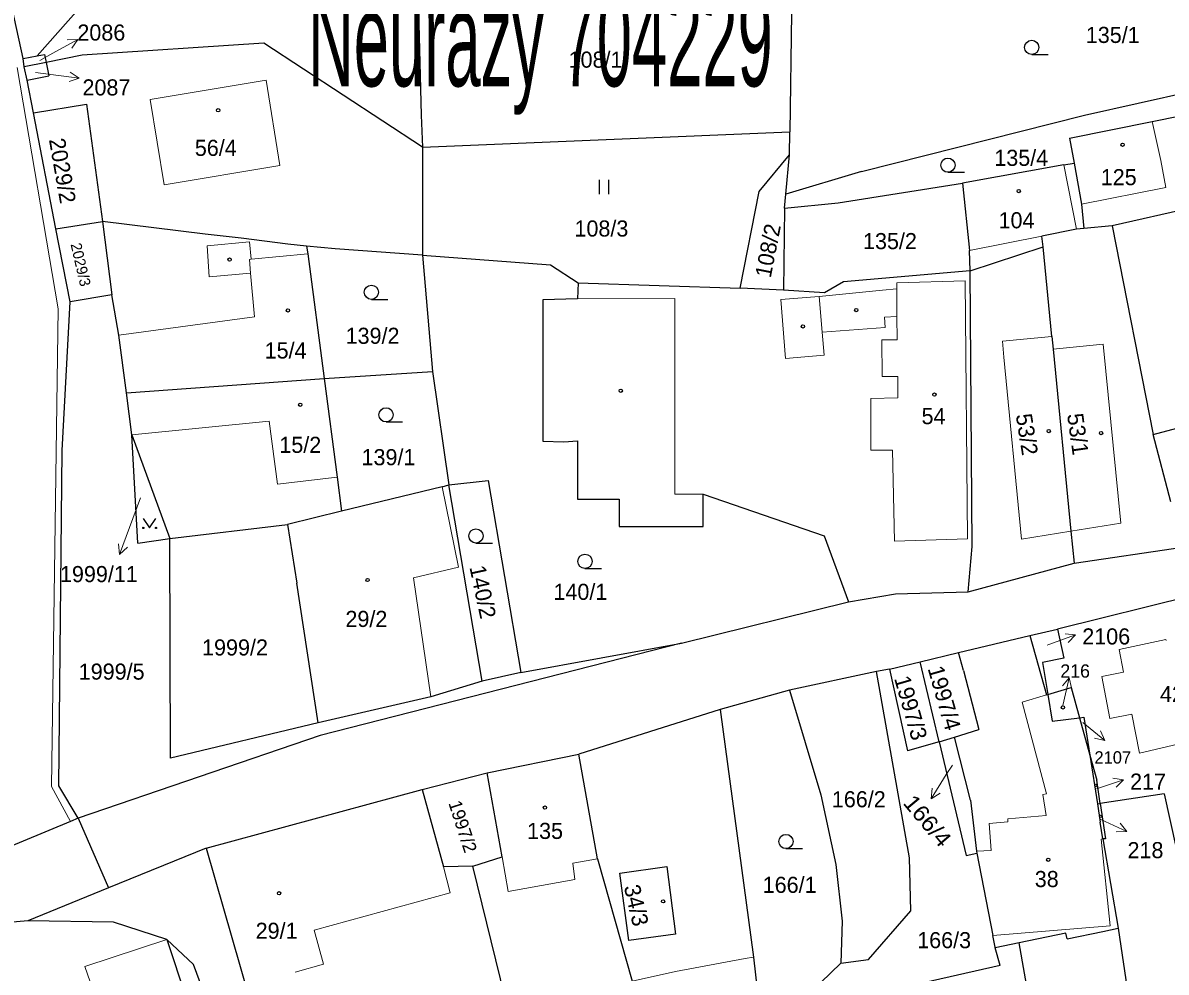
# Model space of a CAD drawing. Extents: x -820420 to -815896, y -1105820 to -1103643.
# Drawn here: x -817654.9 to -817534.2, y -1104919.6 to -1104819.4 of the extents above; entities that cross this region are included whole.
import ezdxf
from ezdxf.enums import TextEntityAlignment as Align

# ---------------------------------------------------------------- set-up
doc = ezdxf.new("R2010")
doc.units = 0
doc.header["$LTSCALE"] = 0.68
for name, color, linetype, lineweight in [('1', 7, 'Continuous', 25), ('3', 7, 'Continuous', 25), ('4', 7, 'Continuous', 13), ('5', 7, 'Continuous', 25), ('7', 7, 'Continuous', 13)]:
    doc.layers.add(name, color=color, linetype=linetype, lineweight=lineweight)
doc.layers.add('2', color=7, linetype='Continuous')

msp = doc.modelspace()

# ---------------------------------------------------------------- linework, layer by layer
at = {"layer": '1'}
for p, q in [((-817654.9, -1104823.17), (-817658.74, -1104805.43)), ((-817653.43, -1104822.89), (-817640.64, -1104808.45)), ((-817613.34, -1104810.6), (-817612.89, -1104829.14)), ((-817573.78, -1104818.38), (-817573.97, -1104830.9)), ((-817629.5, -1104821.54), (-817648.67, -1104822.8)), ((-817612.76, -1104832.53), (-817629.5, -1104821.54)), ((-817654.9, -1104823.17), (-817653.43, -1104822.89)), ((-817654.78, -1104824.05), (-817654.9, -1104823.17)), ((-817653.43, -1104822.89), (-817652.64, -1104822.74)), ((-817652.64, -1104822.74), (-817652.48, -1104823.58)), ((-817648.67, -1104822.8), (-817652.48, -1104823.58)), ((-817542.88, -1104829.13), (-817516.28, -1104823.19)), ((-817652.48, -1104823.58), (-817654.78, -1104824.05)), ((-817654.47, -1104825.45), (-817654.78, -1104824.05)), ((-817652.48, -1104823.58), (-817652.19, -1104824.98)), ((-817654.47, -1104825.45), (-817652.19, -1104824.98)), ((-817653.82, -1104828.9), (-817654.47, -1104825.45)), ((-817653.82, -1104828.9), (-817648.21, -1104827.97)), ((-817648.21, -1104827.97), (-817646.54, -1104840.38)), ((-817651.45, -1104841.15), (-817653.82, -1104828.9)), ((-817612.89, -1104829.14), (-817612.76, -1104832.53)), ((-817566.42, -1104835.1), (-817542.88, -1104829.13)), ((-817535.71, -1104829.81), (-817532.77, -1104829.22)), ((-817544.44, -1104831.56), (-817535.71, -1104829.81)), ((-817612.76, -1104832.53), (-817573.97, -1104830.9)), ((-817574.01, -1104833.33), (-817573.97, -1104830.9)), ((-817544.44, -1104831.56), (-817543.97, -1104834.2)), ((-817612.76, -1104832.53), (-817612.75, -1104843.92)), ((-817577.19, -1104837.21), (-817574.01, -1104833.33)), ((-817574.4, -1104837.48), (-817574.01, -1104833.33)), ((-817566.42, -1104835.1), (-817574.4, -1104837.48)), ((-817545.03, -1104834.37), (-817555.75, -1104836.32)), ((-817545.03, -1104834.37), (-817543.97, -1104834.2)), ((-817543.97, -1104834.2), (-817543.19, -1104838.54)), ((-817568.85, -1104838.39), (-817555.75, -1104836.32)), ((-817555.75, -1104836.32), (-817555.02, -1104843.43)), ((-817574.54, -1104838.95), (-817574.4, -1104837.48)), ((-817574.54, -1104838.95), (-817574.65, -1104847.61)), ((-817574.54, -1104838.95), (-817568.85, -1104838.39)), ((-817543.19, -1104838.54), (-817542.92, -1104841.11)), ((-817530.88, -1104838.78), (-817539.93, -1104840.84)), ((-817651.45, -1104841.15), (-817646.54, -1104840.38)), ((-817649.93, -1104848.83), (-817651.45, -1104841.15)), ((-817646.54, -1104840.38), (-817645.55, -1104848.1)), ((-817635.7, -1104841.71), (-817646.54, -1104840.38)), ((-817543.7, -1104841.18), (-817547.36, -1104841.9)), ((-817542.92, -1104841.11), (-817543.7, -1104841.18)), ((-817539.93, -1104840.84), (-817542.92, -1104841.11)), ((-817539.93, -1104840.84), (-817535.62, -1104862.85)), ((-817631.9, -1104842.12), (-817635.7, -1104841.71)), ((-817626.97, -1104842.77), (-817631.9, -1104842.12)), ((-817547.21, -1104843.03), (-817547.36, -1104841.9)), ((-817624.99, -1104842.97), (-817626.97, -1104842.77)), ((-817624.99, -1104842.97), (-817624.86, -1104843.79)), ((-817621.97, -1104843.25), (-817624.99, -1104842.97)), ((-817624.86, -1104843.79), (-817623.13, -1104856.95)), ((-817612.75, -1104843.92), (-817621.97, -1104843.25)), ((-817554.94, -1104845.57), (-817555.02, -1104843.43)), ((-817554.94, -1104845.57), (-817547.21, -1104843.03)), ((-817546.3, -1104852.5), (-817547.21, -1104843.03)), ((-817612.75, -1104843.92), (-817599.23, -1104844.93)), ((-817612.75, -1104843.92), (-817611.69, -1104856.18)), ((-817599.23, -1104844.93), (-817596.33, -1104846.83)), ((-817554.94, -1104845.57), (-817568.31, -1104846.74)), ((-817554.73, -1104874.66), (-817554.94, -1104845.57)), ((-817596.33, -1104846.83), (-817596.38, -1104848.54)), ((-817596.33, -1104846.83), (-817579.2, -1104847.41)), ((-817568.31, -1104846.74), (-817570.32, -1104847.88)), ((-817645.55, -1104848.1), (-817649.93, -1104848.83)), ((-817644.79, -1104852.37), (-817645.55, -1104848.1)), ((-817596.38, -1104848.54), (-817600.05, -1104848.64)), ((-817600.05, -1104848.64), (-817600.03, -1104863.53)), ((-817570.32, -1104847.88), (-817574.65, -1104847.61)), ((-817650.79, -1104864.54), (-817649.93, -1104848.83)), ((-817643.99, -1104858.45), (-817644.79, -1104852.37)), ((-817546.3, -1104852.5), (-817546.17, -1104853.85)), ((-817546.17, -1104853.85), (-817544.31, -1104873.05)), ((-817535.62, -1104862.85), (-817509.39, -1104855.82)), ((-817643.99, -1104858.45), (-817623.13, -1104856.95)), ((-817623.13, -1104856.95), (-817611.69, -1104856.18)), ((-817623.13, -1104856.95), (-817621.77, -1104867.34)), ((-817611.69, -1104856.18), (-817609.98, -1104868.15)), ((-817643.43, -1104862.87), (-817643.99, -1104858.45)), ((-817642.8, -1104874.31), (-817643.43, -1104862.87)), ((-817643.43, -1104862.87), (-817639.42, -1104873.82)), ((-817533.76, -1104869.95), (-817535.62, -1104862.85)), ((-817600.03, -1104863.53), (-817597.84, -1104863.63)), ((-817597.84, -1104863.63), (-817596.37, -1104863.51)), ((-817596.37, -1104863.51), (-817596.37, -1104869.66)), ((-817651.15, -1104899.91), (-817650.79, -1104864.54)), ((-817621.77, -1104867.34), (-817621.3, -1104870.93)), ((-817609.98, -1104868.15), (-817605.81, -1104867.7)), ((-817605.81, -1104867.7), (-817602.36, -1104887.97)), ((-817610.68, -1104868.37), (-817621.3, -1104870.93)), ((-817610.68, -1104868.37), (-817609.98, -1104868.15)), ((-817606.45, -1104888.88), (-817609.98, -1104868.15)), ((-817583.12, -1104869.15), (-817570.34, -1104873.54)), ((-817583.12, -1104872.54), (-817583.12, -1104869.15)), ((-817596.37, -1104869.66), (-817591.99, -1104869.66)), ((-817591.99, -1104869.66), (-817591.99, -1104872.55)), ((-817621.3, -1104870.93), (-817627, -1104872.33)), ((-817591.99, -1104872.55), (-817583.12, -1104872.54)), ((-817642.8, -1104874.31), (-817639.42, -1104873.82)), ((-817639.36, -1104897), (-817639.42, -1104873.82)), ((-817570.34, -1104873.54), (-817567.78, -1104880.49)), ((-817544.31, -1104873.05), (-817543.97, -1104876.41)), ((-817555.13, -1104879.43), (-817554.73, -1104874.66)), ((-817543.97, -1104876.41), (-817532.5, -1104874.73)), ((-817555.13, -1104879.43), (-817543.97, -1104876.41)), ((-817623.76, -1104893.26), (-817626.03, -1104878.52)), ((-817530.11, -1104879.52), (-817545.73, -1104883.38)), ((-817585.42, -1104884.86), (-817567.78, -1104880.49)), ((-817585.42, -1104884.86), (-817623.55, -1104894.62)), ((-817602.36, -1104887.97), (-817585.42, -1104884.86)), ((-817556.17, -1104885.85), (-817548.63, -1104884.07)), ((-817548.63, -1104884.07), (-817546.87, -1104890.32)), ((-817560.22, -1104886.83), (-817556.17, -1104885.85)), ((-817555.65, -1104887.76), (-817556.17, -1104885.85)), ((-817563.45, -1104887.61), (-817560.22, -1104886.83)), ((-817558.21, -1104895.27), (-817560.22, -1104886.83)), ((-817545.05, -1104886.46), (-817547.28, -1104886.9)), ((-817547.28, -1104886.9), (-817546.74, -1104890.28)), ((-817602.36, -1104887.97), (-817606.45, -1104888.88)), ((-817564.82, -1104887.87), (-817574.01, -1104889.84)), ((-817563.45, -1104887.61), (-817564.82, -1104887.87)), ((-817561.35, -1104907.52), (-817564.82, -1104887.87)), ((-817563.45, -1104887.61), (-817561.56, -1104896.24)), ((-817555.65, -1104887.76), (-817554.01, -1104893.97)), ((-817606.45, -1104888.88), (-817611.88, -1104890.54)), ((-817546.74, -1104890.28), (-817544.28, -1104889.56)), ((-817544.28, -1104889.56), (-817543.4, -1104892.74)), ((-817611.88, -1104890.54), (-817623.76, -1104893.26)), ((-817574.01, -1104889.84), (-817581.32, -1104891.87)), ((-817574.01, -1104889.84), (-817570.68, -1104900.87)), ((-817546.87, -1104890.32), (-817546.74, -1104890.28)), ((-817546.74, -1104890.28), (-817546.29, -1104893.08)), ((-817581.32, -1104891.87), (-817596.25, -1104896.58)), ((-817581.32, -1104891.87), (-817577.81, -1104917.99)), ((-817623.76, -1104893.26), (-817639.36, -1104897)), ((-817546.29, -1104893.08), (-817543.4, -1104892.74)), ((-817543.4, -1104892.74), (-817542.93, -1104892.68)), ((-817543.4, -1104892.74), (-817542.3, -1104896.68)), ((-817623.55, -1104894.62), (-817649.09, -1104903.33)), ((-817558.21, -1104895.27), (-817561.56, -1104896.24)), ((-817554.9, -1104901.44), (-817556.58, -1104894.8)), ((-817605.93, -1104898.54), (-817596.25, -1104896.58)), ((-817594.26, -1104907.62), (-817596.25, -1104896.58)), ((-817542.3, -1104896.68), (-817541.57, -1104899.32)), ((-817612.79, -1104900.31), (-817605.93, -1104898.54)), ((-817604.35, -1104907.42), (-817605.93, -1104898.54)), ((-817541.21, -1104901.78), (-817541.57, -1104899.32)), ((-817649.09, -1104903.33), (-817651.15, -1104899.91)), ((-817635.6, -1104906.5), (-817612.79, -1104900.31)), ((-817612.79, -1104900.31), (-817610.54, -1104908.46)), ((-817570.68, -1104900.87), (-817569.12, -1104908.21)), ((-817554.9, -1104901.44), (-817554.26, -1104906.82)), ((-817541.5, -1104901.82), (-817541.21, -1104901.78)), ((-817534.44, -1104900.75), (-817541.21, -1104901.78)), ((-817541.21, -1104901.78), (-817540.66, -1104905.51)), ((-817534.44, -1104900.75), (-817531.92, -1104912.23)), ((-817541.5, -1104901.82), (-817541.22, -1104903.77)), ((-817649.91, -1104903.67), (-817659.5, -1104907.65)), ((-817649.09, -1104903.33), (-817649.91, -1104903.67)), ((-817649.09, -1104903.33), (-817645.91, -1104910.68)), ((-817540.92, -1104905.53), (-817541.22, -1104903.77)), ((-817635.6, -1104906.5), (-817645.91, -1104910.68)), ((-817635.6, -1104906.5), (-817628.62, -1104930.65)), ((-817540.66, -1104905.51), (-817540.92, -1104905.53)), ((-817540.92, -1104905.53), (-817539.31, -1104914.95)), ((-817607.42, -1104908.4), (-817604.35, -1104907.42)), ((-817594.26, -1104907.62), (-817590.63, -1104920.54)), ((-817561.19, -1104913.11), (-817561.35, -1104907.52)), ((-817554.26, -1104906.82), (-817554.22, -1104907.03)), ((-817554.22, -1104907.03), (-817552.54, -1104915.72)), ((-817607.42, -1104908.4), (-817610.54, -1104908.46)), ((-817603.85, -1104922.94), (-817607.42, -1104908.4)), ((-817591.93, -1104909.12), (-817586.97, -1104908.43)), ((-817586.97, -1104908.43), (-817586.03, -1104915.58)), ((-817569.12, -1104908.21), (-817568.43, -1104914.19)), ((-817590.97, -1104916.25), (-817591.93, -1104909.12)), ((-817645.91, -1104910.68), (-817654.42, -1104914.15)), ((-817565.67, -1104918.24), (-817561.19, -1104913.11)), ((-817654.42, -1104914.15), (-817660, -1104914.69)), ((-817645.35, -1104914.31), (-817654.42, -1104914.15)), ((-817639.74, -1104916.15), (-817645.35, -1104914.31)), ((-817568.43, -1104914.19), (-817568.58, -1104918.64)), ((-817540.92, -1104915.28), (-817539.31, -1104914.95)), ((-817539.31, -1104914.95), (-817536.86, -1104931.17)), ((-817639.74, -1104916.15), (-817636.91, -1104918.76)), ((-817639.74, -1104916.15), (-817636.38, -1104926.16)), ((-817586.03, -1104915.58), (-817590.97, -1104916.25)), ((-817552.3, -1104916.96), (-817552.54, -1104915.72)), ((-817544.82, -1104915.48), (-817549.77, -1104916.5)), ((-817544.7, -1104916.06), (-817544.82, -1104915.48)), ((-817544.7, -1104916.06), (-817540.92, -1104915.28)), ((-817552.28, -1104917.02), (-817552.3, -1104916.96)), ((-817549.77, -1104916.5), (-817552.28, -1104917.02)), ((-817551.75, -1104918.88), (-817552.28, -1104917.02)), ((-817548.33, -1104924.49), (-817549.77, -1104916.5)), ((-817577.81, -1104917.99), (-817577.4, -1104921.73)), ((-817568.58, -1104918.64), (-817570.71, -1104920.67)), ((-817568.58, -1104918.64), (-817565.67, -1104918.24)), ((-817633.72, -1104927.48), (-817636.91, -1104918.76)), ((-817551.75, -1104918.88), (-817563.41, -1104921.51))]:
    msp.add_line(p, q, dxfattribs=at)
for points in [[(-817574.65, -1104847.61), (-817579.2, -1104847.41), (-817577.19, -1104837.21)], [(-817639.42, -1104873.82), (-817627, -1104872.33), (-817626.03, -1104878.52)], [(-817567.78, -1104880.49), (-817562.83, -1104879.65), (-817555.13, -1104879.43)], [(-817548.63, -1104884.07), (-817545.73, -1104883.38), (-817545.05, -1104886.46)], [(-817542.93, -1104892.68), (-817542.3, -1104896.68), (-817541.5, -1104901.82)], [(-817558.21, -1104895.27), (-817556.58, -1104894.8), (-817554.01, -1104893.97)], [(-817558.21, -1104895.27), (-817555.36, -1104907.28), (-817554.22, -1104907.03)]]:
    msp.add_lwpolyline(points, dxfattribs=at)
at = {"layer": '3'}
for p, q in [((-817548.433, -1104822.74), (-817546.683, -1104822.74)), ((-817557.283, -1104835.17), (-817555.533, -1104835.17)), ((-817594.061, -1104837.47), (-817594.061, -1104835.97)), ((-817593.06, -1104837.47), (-817593.06, -1104835.97)), ((-817618.143, -1104848.58), (-817616.393, -1104848.58)), ((-817616.593, -1104861.52), (-817614.843, -1104861.52)), ((-817607.103, -1104874.3), (-817605.353, -1104874.3)), ((-817595.593, -1104876.98), (-817593.843, -1104876.98)), ((-817574.383, -1104906.54), (-817572.633, -1104906.54))]:
    msp.add_line(p, q, dxfattribs=at)
msp.add_lwpolyline([(-817642.22, -1104871.694), (-817641.55, -1104872.7), (-817640.88, -1104871.694)], dxfattribs=at)
for centre, radius in [((-817548.4329, -1104821.9898), 0.75), ((-817557.2829, -1104834.4198), 0.75), ((-817618.1429, -1104847.8298), 0.75), ((-817616.5929, -1104860.7698), 0.75), ((-817642.22, -1104872.6996), 0.067), ((-817640.88, -1104872.6996), 0.067), ((-817607.1029, -1104873.5498), 0.75), ((-817595.5929, -1104876.2298), 0.75), ((-817574.3829, -1104905.7898), 0.75)]:
    msp.add_circle(centre, radius, dxfattribs=at)
at = {"layer": '4'}
for p, q in [((-817651.2, -1104849.57), (-817655.55, -1104824.12)), ((-817641.49, -1104827.48), (-817629.24, -1104825.44)), ((-817629.24, -1104825.44), (-817627.8, -1104834.47)), ((-817640.03, -1104836.5), (-817641.49, -1104827.48)), ((-817640.03, -1104836.5), (-817627.8, -1104834.47)), ((-817543.7, -1104841.18), (-817545.03, -1104834.37)), ((-817543.19, -1104838.54), (-817534.26, -1104836.77)), ((-817631.02, -1104842.52), (-817635.47, -1104842.93)), ((-817631.02, -1104842.52), (-817630.85, -1104844.35)), ((-817555.02, -1104843.43), (-817547.36, -1104841.9)), ((-817635.47, -1104842.93), (-817635.26, -1104846.22)), ((-817630.85, -1104844.35), (-817624.86, -1104843.79)), ((-817631.02, -1104844.37), (-817630.85, -1104844.35)), ((-817631.02, -1104844.37), (-817630.89, -1104845.83)), ((-817635.26, -1104846.22), (-817630.89, -1104845.83)), ((-817630.89, -1104845.83), (-817630.48, -1104850.44)), ((-817562.69, -1104847.48), (-817562.68, -1104846.83)), ((-817562.68, -1104846.83), (-817555.46, -1104846.61)), ((-817555.46, -1104846.61), (-817555.2, -1104873.87)), ((-817596.38, -1104848.54), (-817586.11, -1104848.5)), ((-817586.11, -1104848.5), (-817586.11, -1104869.15)), ((-817574.91, -1104848.61), (-817570.88, -1104848.29)), ((-817574.42, -1104854.83), (-817574.91, -1104848.61)), ((-817570.88, -1104848.29), (-817564.17, -1104847.62)), ((-817570.88, -1104848.29), (-817570.56, -1104852.04)), ((-817564.17, -1104847.62), (-817562.69, -1104847.48)), ((-817651.92, -1104900), (-817651.2, -1104849.57)), ((-817644.79, -1104852.37), (-817630.48, -1104850.44)), ((-817563.96, -1104850.45), (-817563.9, -1104851.55)), ((-817562.65, -1104852.84), (-817562.67, -1104850.38)), ((-817563.9, -1104851.55), (-817570.56, -1104852.04)), ((-817570.56, -1104852.04), (-817570.35, -1104854.48)), ((-817564.24, -1104852.85), (-817562.65, -1104852.84)), ((-817564.22, -1104856.73), (-817564.24, -1104852.85)), ((-817546.3, -1104852.5), (-817551.52, -1104853.01)), ((-817551.52, -1104853.01), (-817551.38, -1104854.7)), ((-817546.17, -1104853.85), (-817540.89, -1104853.32)), ((-817540.89, -1104853.32), (-817539.04, -1104872.2)), ((-817570.35, -1104854.48), (-817574.42, -1104854.83)), ((-817551.38, -1104854.7), (-817549.5, -1104873.89)), ((-817562.58, -1104856.72), (-817564.22, -1104856.73)), ((-817562.56, -1104858.98), (-817562.58, -1104856.72)), ((-817565.43, -1104859.04), (-817562.56, -1104858.98)), ((-817565.42, -1104864.49), (-817565.43, -1104859.04)), ((-817643.43, -1104862.87), (-817628.95, -1104861.43)), ((-817628.95, -1104861.43), (-817628.07, -1104868.09)), ((-817563.12, -1104864.48), (-817565.42, -1104864.49)), ((-817562.93, -1104874.09), (-817563.12, -1104864.48)), ((-817628.07, -1104868.09), (-817621.77, -1104867.34)), ((-817583.12, -1104869.15), (-817586.11, -1104869.15)), ((-817544.31, -1104873.05), (-817539.04, -1104872.2)), ((-817562.93, -1104874.09), (-817555.2, -1104873.87)), ((-817549.5, -1104873.89), (-817544.31, -1104873.05)), ((-817611.88, -1104890.54), (-817613.69, -1104877.96)), ((-817534.27, -1104884.46), (-817539.22, -1104885.54)), ((-817534.23, -1104884.6), (-817534.27, -1104884.46)), ((-817539.22, -1104885.54), (-817538.75, -1104887.93)), ((-817538.75, -1104887.93), (-817541.03, -1104888.39)), ((-817541.03, -1104888.39), (-817540.18, -1104892.81)), ((-817546.87, -1104890.32), (-817549.46, -1104891.08)), ((-817549.46, -1104891.08), (-817546.87, -1104900.77)), ((-817540.18, -1104892.81), (-817537.87, -1104892.36)), ((-817537.87, -1104892.36), (-817537.06, -1104896.49)), ((-817533.01, -1104895.54), (-817537.06, -1104896.49)), ((-817649.91, -1104903.67), (-817651.92, -1104900)), ((-817546.87, -1104900.77), (-817547.27, -1104900.85)), ((-817547.27, -1104900.85), (-817546.92, -1104903.05)), ((-817550.95, -1104903.72), (-817552.93, -1104903.9)), ((-817552.93, -1104903.9), (-817552.7, -1104906.74)), ((-817546.92, -1104903.05), (-817550.97, -1104903.4)), ((-817550.97, -1104903.4), (-817550.95, -1104903.72)), ((-817541.11, -1104905.56), (-817540.92, -1104905.53)), ((-817540.14, -1104914.71), (-817541.11, -1104905.56)), ((-817603.7, -1104911.07), (-817604.35, -1104907.42)), ((-817594.26, -1104907.62), (-817596.89, -1104908.08)), ((-817554.26, -1104906.82), (-817552.7, -1104906.74)), ((-817609.82, -1104911.2), (-817610.54, -1104908.46)), ((-817596.89, -1104908.08), (-817596.67, -1104909.79)), ((-817596.67, -1104909.79), (-817603.7, -1104911.07)), ((-817624.17, -1104915.15), (-817609.82, -1104911.2)), ((-817552.54, -1104915.72), (-817540.14, -1104914.71)), ((-817648.4, -1104919), (-817639.74, -1104916.15)), ((-817623.18, -1104918.75), (-817624.17, -1104915.15)), ((-817578.7, -1104918.13), (-817586.04, -1104919.51)), ((-817578.7, -1104918.13), (-817577.81, -1104917.99)), ((-817648.4, -1104919), (-817647.04, -1104922.82)), ((-817623.18, -1104918.75), (-817626.2, -1104919.58)), ((-817586.04, -1104919.51), (-817590.63, -1104920.54))]:
    msp.add_line(p, q, dxfattribs=at)
for points in [[(-817535.71, -1104829.81), (-817534.82, -1104833.92), (-817534.26, -1104836.77)], [(-817562.69, -1104847.48), (-817562.67, -1104850.38), (-817563.96, -1104850.45)], [(-817613.69, -1104877.96), (-817608.94, -1104876.85), (-817610.68, -1104868.37)]]:
    msp.add_lwpolyline(points, dxfattribs=at)
at = {"layer": '5'}
for centre, radius in [((-817634.3168, -1104828.6192), 0.175), ((-817538.8468, -1104832.2592), 0.175), ((-817549.7968, -1104837.1492), 0.175), ((-817633.1068, -1104844.3892), 0.175), ((-817626.9468, -1104849.7492), 0.175), ((-817566.9568, -1104849.7092), 0.175), ((-817572.5868, -1104851.4392), 0.175), ((-817591.8168, -1104858.2292), 0.175), ((-817625.6568, -1104859.7092), 0.175), ((-817558.7068, -1104858.6292), 0.175), ((-817546.6368, -1104862.4792), 0.175), ((-817541.1068, -1104862.6992), 0.175), ((-817618.5468, -1104878.1992), 0.175), ((-817545.1468, -1104891.6392), 0.175), ((-817541.6551, -1104899.8794), 0.1313), ((-817599.8168, -1104902.2192), 0.175), ((-817541.1651, -1104903.1294), 0.1313), ((-817546.6868, -1104907.7192), 0.175), ((-817627.8868, -1104911.2592), 0.175), ((-817587.3568, -1104912.1092), 0.175)]:
    msp.add_circle(centre, radius, dxfattribs=at)
at = {"layer": '7'}
for p, q in [((-817649.135, -1104821.145), (-817650.254, -1104821.193)), ((-817648.991, -1104825.226), (-817649.924, -1104824.607)), ((-817644.716, -1104875.49), (-817643.903, -1104874.72)), ((-817543.8, -1104883.994), (-817544.912, -1104883.866)), ((-817544.485, -1104888.506), (-817545.198, -1104889.369)), ((-817540.718, -1104895.129), (-817541.181, -1104894.109)), ((-817538.753, -1104899.273), (-817539.862, -1104899.126)), ((-817559.04, -1104901.285), (-817558.085, -1104900.701)), ((-817538.41, -1104904.738), (-817539.106, -1104903.861))]:
    msp.add_line(p, q, dxfattribs=at)
for points in [[(-817653.14, -1104823.37), (-817651.76, -1104822.6), (-817649.135, -1104821.145), (-817649.768, -1104822.069)], [(-817653.6, -1104824.65), (-817651.97, -1104824.86), (-817648.991, -1104825.226), (-817650.046, -1104825.601)], [(-817642.53, -1104869.51), (-817643.69, -1104872.67), (-817644.716, -1104875.49), (-817644.844, -1104874.378)], [(-817546.81, -1104885.09), (-817546.62, -1104885.02), (-817543.8, -1104883.994), (-817544.57, -1104884.807)], [(-817545.16, -1104891.43), (-817544.485, -1104888.506), (-817544.222, -1104889.594)], [(-817543.05, -1104893.24), (-817540.718, -1104895.129), (-817541.811, -1104894.887)], [(-817556.81, -1104897.74), (-817557.45, -1104898.74), (-817559.04, -1104901.285), (-817558.934, -1104900.17)], [(-817541.59, -1104900.25), (-817538.753, -1104899.273), (-817539.536, -1104900.072)], [(-817541.13, -1104903.47), (-817538.41, -1104904.738), (-817539.529, -1104904.769)]]:
    msp.add_lwpolyline(points, dxfattribs=at)

# ---------------------------------------------------------------- texts
at = {"layer": '2'}
for s, height, p in [('2086', 1.7, (-817649.18, -1104821.275)), ('2087', 1.7, (-817648.64, -1104827.065)), ('2106', 1.7, (-817543.1, -1104885.002)), ('2107', 1.3, (-817541.81, -1104897.571)), ('217', 1.7, (-817538.05, -1104900.322)), ('218', 1.7, (-817538.32, -1104907.555))]:
    msp.add_text(s, height=height, dxfattribs=at).set_placement(p)
for s, height, p in [('135/1', 1.7, (-817539.88, -1104821.525)), ('108/1', 1.7, (-817594.48, -1104824.135)), ('56/4', 1.7, (-817634.569, -1104833.445)), ('135/4', 1.7, (-817549.54, -1104834.495)), ('125', 1.7, (-817539.249, -1104836.535)), ('108/3', 1.7, (-817593.86, -1104841.955)), ('104', 1.7, (-817550.039, -1104841.085)), ('135/2', 1.7, (-817563.4, -1104843.285)), ('139/2', 1.7, (-817618.02, -1104853.275)), ('15/4', 1.7, (-817627.199, -1104854.825)), ('54', 1.7, (-817558.799, -1104861.755)), ('15/2', 1.7, (-817625.649, -1104864.785)), ('139/1', 1.7, (-817616.34, -1104866.085)), ('140/1', 1.7, (-817596.08, -1104880.295)), ('29/2', 1.7, (-817618.669, -1104883.155)), ('1999/2', 1.7, (-817632.54, -1104886.165)), ('1999/5', 1.7, (-817645.56, -1104888.715)), ('216', 1.4, (-817543.85, -1104888.5)), ('42', 1.7, (-817533.629, -1104891.085)), ('166/2', 1.7, (-817566.69, -1104902.185)), ('135', 1.7, (-817599.809, -1104905.525)), ('38', 1.7, (-817546.849, -1104910.605)), ('166/1', 1.7, (-817573.99, -1104911.215)), ('29/1', 1.7, (-817628.149, -1104916.065)), ('166/3', 1.7, (-817557.68, -1104917.055))]:
    msp.add_text(s, height=height, dxfattribs=at).set_placement(p, align=Align.CENTER)
for s, height, rotation, p in [('2029/2', 1.7, 280, (-817651.5848, -1104835.1489)), ('108/2', 1.7, 79, (-817575.4458, -1104843.5987)), ('2029/3', 1.14, 283, (-817649.382, -1104845.0393)), ('53/2', 1.7, 279, (-817549.7783, -1104862.963)), ('53/1', 1.7, 278, (-817544.4016, -1104862.9182)), ('140/2', 1.7, 282, (-817607.2063, -1104879.6278)), ('1997/3', 1.7, 286, (-817562.0144, -1104891.9162)), ('1997/4', 1.7, 286, (-817558.4744, -1104890.8762)), ('1997/2', 1.386, 288, (-817609.1532, -1104904.4259)), ('34/3', 1.7, 283, (-817591.0013, -1104912.7128))]:
    msp.add_text(s, height=height, rotation=rotation, dxfattribs=at).set_placement(p, align=Align.CENTER)
msp.add_text('1999/11', height=1.7, dxfattribs=at).set_placement((-817642.8, -1104878.425), align=Align.RIGHT)
at = {"layer": '2', "width": 1.1}
msp.add_text('166/4', height=1.7, rotation=310, dxfattribs=at).set_placement((-817560.0917, -1104904.1606), align=Align.CENTER)
at = {"layer": '7', "width": 0.5}
msp.add_text('Neurazy 704229', height=10, dxfattribs=at).set_placement((-817600.299, -1104826.093), align=Align.CENTER)

doc.saveas('drawing.dxf')
